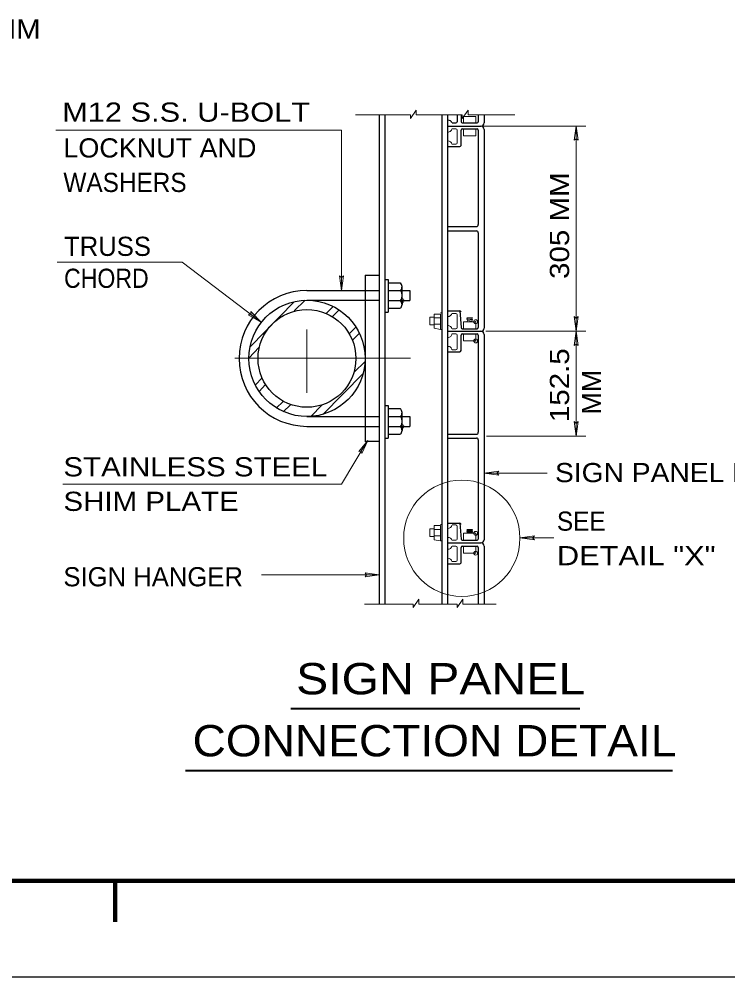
# Model space of a CAD drawing. Extents: x 312601.858 to 312602.699, y 144420.109 to 144420.704.
# Drawn here: x 312602.2633 to 312602.3741, y 144420.1095 to 144420.2593 of the extents above; entities that cross this region are included whole.
import ezdxf
from ezdxf.enums import TextEntityAlignment as Align

# ---------------------------------------------------------------- set-up
doc = ezdxf.new("R2010")
doc.units = 0
doc.header["$LTSCALE"] = 0.0012
doc.header["$PDMODE"] = 32
doc.header["$PDSIZE"] = 0.0006
doc.linetypes.add('DOT_DASHED', pattern=[7.7, 5, -1.2, 0.3, -1.2])
doc.linetypes.add('SHORT_DASHED', pattern=[2.7, 1.5, -1.2])
for name, color, linetype, lineweight in [('1', 7, 'Continuous', 13), ('2', 7, 'Continuous', 13), ('39', 7, 'Continuous', 13)]:
    doc.layers.add(name, color=color, linetype=linetype, lineweight=lineweight)

msp = doc.modelspace()

# ---------------------------------------------------------------- hatches: boundary and pattern name
at = {"layer": '39'}
msp.add_hatch(color=256, dxfattribs=at).paths.add_polyline_path([(312602.2995, 144420.2132), (312602.2995, 144420.2136), (312602.3012, 144420.2119), (312602.2991, 144420.2131)])

# ---------------------------------------------------------------- linework, layer by layer
at = {"layer": '1'}
for p, q in [((312602.3159, 144420.2444), (312602.3245, 144420.2444)), ((312602.3245, 144420.2438), (312602.3254, 144420.2451)), ((312602.3245, 144420.2438), (312602.3245, 144420.2444)), ((312602.3254, 144420.2444), (312602.3254, 144420.2451)), ((312602.3254, 144420.2444), (312602.3326, 144420.2444)), ((312602.3326, 144420.2438), (312602.3335, 144420.2451)), ((312602.3326, 144420.2438), (312602.3326, 144420.2444)), ((312602.3328, 144420.2441), (312602.3328, 144420.2431)), ((312602.3328, 144420.2441), (312602.3347, 144420.2441)), ((312602.3335, 144420.2444), (312602.3335, 144420.2451)), ((312602.3335, 144420.2444), (312602.3408, 144420.2444)), ((312602.3347, 144420.2441), (312602.3347, 144420.2431)), ((312602.3351, 144420.2444), (312602.3351, 144420.2432)), ((312602.269, 144420.242), (312602.3137, 144420.242)), ((312602.3137, 144420.242), (312602.3137, 144420.2169)), ((312602.331, 144420.2422), (312602.3316, 144420.2422)), ((312602.3318, 144420.24), (312602.3318, 144420.242)), ((312602.3328, 144420.2411), (312602.3328, 144420.2422)), ((312602.3328, 144420.2411), (312602.3347, 144420.2411)), ((312602.3347, 144420.2411), (312602.3347, 144420.2422)), ((312602.331, 144420.2398), (312602.3316, 144420.2398)), ((312602.2994, 144420.2081), (312602.3063, 144420.2151)), ((312602.3063, 144420.2137), (312602.308, 144420.2154)), ((312602.3113, 144420.2133), (312602.3124, 144420.2144)), ((312602.3123, 144420.2128), (312602.3133, 144420.2138)), ((312602.3275, 144420.2127), (312602.3275, 144420.2115)), ((312602.3282, 144420.2127), (312602.3275, 144420.2127)), ((312602.3294, 144420.2134), (312602.3292, 144420.2134)), ((312602.331, 144420.2133), (312602.3316, 144420.2133)), ((312602.3318, 144420.2131), (312602.3318, 144420.2111)), ((312602.3149, 144420.2101), (312602.316, 144420.2112)), ((312602.3282, 144420.2115), (312602.3275, 144420.2115)), ((312602.3282, 144420.2126), (312602.3292, 144420.2126)), ((312602.3282, 144420.2116), (312602.3292, 144420.2116)), ((312602.3328, 144420.212), (312602.3328, 144420.2109)), ((312602.3328, 144420.212), (312602.3347, 144420.212)), ((312602.3333, 144420.2126), (312602.3334, 144420.2126)), ((312602.3333, 144420.2124), (312602.3341, 144420.2124)), ((312602.3334, 144420.2126), (312602.3341, 144420.2126)), ((312602.3334, 144420.2122), (312602.3342, 144420.2123)), ((312602.3347, 144420.212), (312602.3347, 144420.2109)), ((312602.3154, 144420.2091), (312602.3165, 144420.2102)), ((312602.3294, 144420.2108), (312602.3292, 144420.2108)), ((312602.331, 144420.2109), (312602.3316, 144420.2109)), ((312602.331, 144420.2101), (312602.3316, 144420.2101)), ((312602.3318, 144420.2078), (312602.3318, 144420.2099)), ((312602.3327, 144420.2109), (312602.3349, 144420.2109)), ((312602.3327, 144420.2101), (312602.3349, 144420.2101)), ((312602.3328, 144420.209), (312602.3328, 144420.2101)), ((312602.3347, 144420.209), (312602.3347, 144420.2101)), ((312602.3363, 144420.2105), (312602.3519, 144420.2105)), ((312602.3328, 144420.209), (312602.3347, 144420.209)), ((312602.2992, 144420.2063), (312602.3008, 144420.208)), ((312602.331, 144420.2076), (312602.3316, 144420.2076)), ((312602.3157, 144420.2041), (312602.3174, 144420.2058)), ((312602.3108, 144420.1975), (312602.3171, 144420.2039)), ((312602.3002, 144420.2021), (312602.3013, 144420.2032)), ((312602.3008, 144420.2011), (312602.3018, 144420.2022)), ((312602.3035, 144420.1985), (312602.3046, 144420.1995)), ((312602.3046, 144420.1979), (312602.3057, 144420.199)), ((312602.3089, 144420.1972), (312602.3107, 144420.199)), ((312602.3177, 144420.1933), (312602.3137, 144420.1866)), ((312602.3364, 144420.1941), (312602.3519, 144420.1941)), ((312602.336, 144420.1883), (312602.3459, 144420.1883)), ((312602.2701, 144420.1866), (312602.3137, 144420.1866)), ((312602.3294, 144420.1803), (312602.3292, 144420.1803)), ((312602.331, 144420.1802), (312602.3316, 144420.1802)), ((312602.3318, 144420.18), (312602.3318, 144420.178)), ((312602.3275, 144420.1796), (312602.3275, 144420.1784)), ((312602.3282, 144420.1796), (312602.3275, 144420.1796)), ((312602.3282, 144420.1784), (312602.3275, 144420.1784)), ((312602.3282, 144420.1795), (312602.3292, 144420.1795)), ((312602.3282, 144420.1785), (312602.3292, 144420.1785)), ((312602.3328, 144420.1789), (312602.3328, 144420.1778)), ((312602.3328, 144420.1789), (312602.3347, 144420.1789)), ((312602.3333, 144420.1794), (312602.3334, 144420.1795)), ((312602.3333, 144420.1792), (312602.3341, 144420.1792)), ((312602.3334, 144420.1795), (312602.3342, 144420.1795)), ((312602.3334, 144420.1793), (312602.3342, 144420.1793)), ((312602.3334, 144420.1791), (312602.3342, 144420.1791)), ((312602.3347, 144420.1789), (312602.3347, 144420.1778)), ((312602.3416, 144420.1782), (312602.3469, 144420.1782)), ((312602.3294, 144420.1777), (312602.3292, 144420.1777)), ((312602.331, 144420.1778), (312602.3316, 144420.1778)), ((312602.331, 144420.1769), (312602.3316, 144420.1769)), ((312602.3318, 144420.1747), (312602.3318, 144420.1767)), ((312602.3327, 144420.1778), (312602.3349, 144420.1778)), ((312602.3328, 144420.1758), (312602.3328, 144420.1769)), ((312602.3347, 144420.1758), (312602.3347, 144420.1769)), ((312602.3328, 144420.1758), (312602.3347, 144420.1758)), ((312602.331, 144420.1745), (312602.3316, 144420.1745)), ((312602.3012, 144420.1724), (312602.3196, 144420.1724)), ((312602.3173, 144420.1678), (312602.3249, 144420.1678)), ((312602.3249, 144420.1673), (312602.3258, 144420.1686)), ((312602.3249, 144420.1673), (312602.3249, 144420.1678)), ((312602.3258, 144420.1678), (312602.3258, 144420.1686)), ((312602.3258, 144420.1678), (312602.3318, 144420.1678)), ((312602.3318, 144420.1673), (312602.3327, 144420.1686)), ((312602.3318, 144420.1673), (312602.3318, 144420.1678)), ((312602.3327, 144420.1678), (312602.3327, 144420.1686)), ((312602.3327, 144420.1678), (312602.3379, 144420.1678))]:
    msp.add_line(p, q, dxfattribs=at)
at = {"layer": '1', "lineweight": 25}
for p, q in [((312602.3196, 144420.2444), (312602.3196, 144420.1678)), ((312602.3205, 144420.2444), (312602.3205, 144420.1678)), ((312602.3294, 144420.2444), (312602.3294, 144420.1678)), ((312602.3303, 144420.2444), (312602.3303, 144420.2272)), ((312602.3318, 144420.2444), (312602.3318, 144420.2433)), ((312602.3324, 144420.2444), (312602.3324, 144420.2433)), ((312602.3351, 144420.2444), (312602.3351, 144420.2433)), ((312602.336, 144420.2444), (312602.336, 144420.2431)), ((312602.3303, 144420.2426), (312602.3355, 144420.2426)), ((312602.331, 144420.2431), (312602.3316, 144420.2431)), ((312602.3326, 144420.2431), (312602.3349, 144420.2431)), ((312602.3324, 144420.2396), (312602.3324, 144420.242)), ((312602.3326, 144420.2422), (312602.3349, 144420.2422)), ((312602.3351, 144420.242), (312602.3351, 144420.2282)), ((312602.3351, 144420.242), (312602.3351, 144420.2272)), ((312602.336, 144420.2421), (312602.336, 144420.211)), ((312602.3303, 144420.2394), (312602.3322, 144420.2394)), ((312602.3303, 144420.2272), (312602.3303, 144420.1947)), ((312602.3303, 144420.2269), (312602.3348, 144420.2269)), ((312602.3303, 144420.2262), (312602.3348, 144420.2262)), ((312602.3351, 144420.2259), (312602.3351, 144420.2111)), ((312602.3351, 144420.2248), (312602.3351, 144420.2111)), ((312602.3174, 144420.2193), (312602.3174, 144420.1932)), ((312602.3174, 144420.2193), (312602.3196, 144420.2193)), ((312602.3205, 144420.2186), (312602.321, 144420.2186)), ((312602.321, 144420.2181), (312602.3229, 144420.2181)), ((312602.3232, 144420.2169), (312602.3232, 144420.2175)), ((312602.3083, 144420.2169), (312602.3174, 144420.2169)), ((312602.321, 144420.2169), (312602.323, 144420.2169)), ((312602.323, 144420.2169), (312602.3232, 144420.2169)), ((312602.3232, 144420.2153), (312602.3232, 144420.2169)), ((312602.3244, 144420.2169), (312602.3244, 144420.2153)), ((312602.3083, 144420.2154), (312602.3174, 144420.2154)), ((312602.323, 144420.2153), (312602.3232, 144420.2153)), ((312602.3232, 144420.2153), (312602.3232, 144420.2147)), ((312602.3205, 144420.2135), (312602.321, 144420.2135)), ((312602.321, 144420.2141), (312602.3229, 144420.2141)), ((312602.3303, 144420.2105), (312602.3357, 144420.2105)), ((312602.3324, 144420.2075), (312602.3324, 144420.2099)), ((312602.3326, 144420.2109), (312602.3349, 144420.2109)), ((312602.3326, 144420.2101), (312602.3349, 144420.2101)), ((312602.3351, 144420.2099), (312602.3351, 144420.1947)), ((312602.336, 144420.21), (312602.336, 144420.1779)), ((312602.3303, 144420.2073), (312602.3322, 144420.2073)), ((312602.3205, 144420.1989), (312602.321, 144420.1989)), ((312602.321, 144420.1984), (312602.3229, 144420.1984)), ((312602.3232, 144420.1972), (312602.3232, 144420.1978)), ((312602.3083, 144420.1972), (312602.3174, 144420.1972)), ((312602.321, 144420.1972), (312602.323, 144420.1972)), ((312602.323, 144420.1972), (312602.3232, 144420.1972)), ((312602.3232, 144420.1956), (312602.3232, 144420.1972)), ((312602.3244, 144420.1972), (312602.3244, 144420.1956)), ((312602.3083, 144420.1956), (312602.3174, 144420.1956)), ((312602.323, 144420.1956), (312602.3232, 144420.1956)), ((312602.3232, 144420.1956), (312602.3232, 144420.195)), ((312602.3303, 144420.1947), (312602.3303, 144420.1678)), ((312602.3174, 144420.1933), (312602.3196, 144420.1933)), ((312602.3205, 144420.1938), (312602.321, 144420.1938)), ((312602.321, 144420.1944), (312602.3229, 144420.1944)), ((312602.3303, 144420.1944), (312602.3348, 144420.1944)), ((312602.3303, 144420.1938), (312602.3348, 144420.1938)), ((312602.3351, 144420.1935), (312602.3351, 144420.178)), ((312602.3351, 144420.1932), (312602.3351, 144420.178)), ((312602.3303, 144420.1774), (312602.3355, 144420.1774)), ((312602.3324, 144420.1743), (312602.3324, 144420.1767)), ((312602.3326, 144420.1778), (312602.3349, 144420.1778)), ((312602.3326, 144420.1769), (312602.3349, 144420.1769)), ((312602.3327, 144420.1769), (312602.3349, 144420.1769)), ((312602.3351, 144420.1767), (312602.3351, 144420.1678)), ((312602.336, 144420.1769), (312602.336, 144420.1678)), ((312602.3303, 144420.1741), (312602.3322, 144420.1741))]:
    msp.add_line(p, q, dxfattribs=at)
at = {"layer": '1', "linetype": 'SHORT_DASHED', "lineweight": 25}
for p, q in [((312602.3174, 144420.2169), (312602.3196, 144420.2169)), ((312602.3174, 144420.2154), (312602.3196, 144420.2154)), ((312602.3174, 144420.1972), (312602.3196, 144420.1972)), ((312602.3174, 144420.1956), (312602.3196, 144420.1956))]:
    msp.add_line(p, q, dxfattribs=at)
at = {"layer": '1', "linetype": 'DOT_DASHED'}
for p, q in [((312602.3083, 144420.2009), (312602.3083, 144420.2108)), ((312602.297, 144420.2063), (312602.3245, 144420.2063))]:
    msp.add_line(p, q, dxfattribs=at)
at = {"layer": '1'}
for points in [[(312602.3303, 144420.2426), (312602.3357, 144420.2426), (312602.3519, 144420.2426)], [(312602.3504, 144420.2426), (312602.3504, 144420.2105), (312602.3504, 144420.1941)], [(312602.3333, 144420.212), (312602.3334, 144420.2122), (312602.3333, 144420.2124), (312602.3334, 144420.2125), (312602.3333, 144420.2126)], [(312602.3333, 144420.212), (312602.3341, 144420.2121), (312602.3341, 144420.2121)], [(312602.3334, 144420.2126), (312602.3342, 144420.2126), (312602.3341, 144420.2126)], [(312602.3341, 144420.2121), (312602.3342, 144420.2123), (312602.3341, 144420.2124), (312602.3342, 144420.2126)], [(312602.3333, 144420.1794), (312602.3341, 144420.1794), (312602.3342, 144420.1791), (312602.3341, 144420.1792)], [(312602.3333, 144420.1789), (312602.3334, 144420.1791), (312602.3333, 144420.1792), (312602.3334, 144420.1793), (312602.3333, 144420.1794)], [(312602.3333, 144420.1789), (312602.3341, 144420.179), (312602.3341, 144420.179)], [(312602.3341, 144420.1792), (312602.3342, 144420.1793), (312602.3341, 144420.1794), (312602.3342, 144420.1795)], [(312602.3303, 144420.1774), (312602.3346, 144420.1774), (312602.3355, 144420.1774)]]:
    msp.add_lwpolyline(points, dxfattribs=at)
for points in [[(312602.3501, 144420.2404), (312602.3504, 144420.2426), (312602.3507, 144420.2404), (312602.3504, 144420.2406)], [(312602.314, 144420.2192), (312602.3137, 144420.2169), (312602.3134, 144420.2192), (312602.3137, 144420.2189)], [(312602.3282, 144420.2132), (312602.3292, 144420.2132), (312602.3292, 144420.2108), (312602.3282, 144420.211)], [(312602.3507, 144420.2128), (312602.3504, 144420.2105), (312602.3501, 144420.2128), (312602.3504, 144420.2125)], [(312602.3501, 144420.2083), (312602.3504, 144420.2105), (312602.3507, 144420.2083), (312602.3504, 144420.2085)], [(312602.3507, 144420.1964), (312602.3504, 144420.1941), (312602.3501, 144420.1964), (312602.3504, 144420.1961)], [(312602.3164, 144420.1917), (312602.3178, 144420.1934), (312602.3169, 144420.1914), (312602.3168, 144420.1918)], [(312602.3383, 144420.188), (312602.336, 144420.1883), (312602.3383, 144420.1886), (312602.338, 144420.1883)], [(312602.3282, 144420.1801), (312602.3292, 144420.1801), (312602.3292, 144420.1777), (312602.3282, 144420.1779)], [(312602.3439, 144420.1779), (312602.3416, 144420.1782), (312602.3439, 144420.1785), (312602.3436, 144420.1782)], [(312602.3174, 144420.1727), (312602.3196, 144420.1724), (312602.3174, 144420.1721), (312602.3176, 144420.1724)]]:
    msp.add_lwpolyline(points, close=True, dxfattribs=at)
at = {"layer": '1', "lineweight": 25}
for points in [[(312602.323, 144420.2169), (312602.3232, 144420.2169), (312602.3244, 144420.2169)], [(312602.321, 144420.2153), (312602.323, 144420.2153), (312602.3244, 144420.2153)], [(312602.3303, 144420.2137), (312602.3322, 144420.2137), (312602.3324, 144420.2111)], [(312602.323, 144420.1972), (312602.3232, 144420.1972), (312602.3244, 144420.1972)], [(312602.321, 144420.1956), (312602.323, 144420.1956), (312602.3244, 144420.1956)], [(312602.3303, 144420.1805), (312602.3322, 144420.1805), (312602.3324, 144420.178)]]:
    msp.add_lwpolyline(points, dxfattribs=at)
for radius in [0.009095, 0.00765]:
    msp.add_circle((312602.3083, 144420.20626), radius, dxfattribs=at)
at = {"layer": '1'}
msp.add_circle((312602.332525, 144420.178125), 0.009095, dxfattribs=at)
at = {"layer": '1', "lineweight": 25}
for centre, radius, start, end in [((312602.3316, 144420.2433), 0.0002, 270, 0), ((312602.3326, 144420.2433), 0.0002, 180, 270), ((312602.3349, 144420.2433), 0.0002, 270, 0), ((312602.3355, 144420.2431), 0.0005, 270, 0), ((312602.3355, 144420.2421), 0.0005, 0, 90), ((312602.3326, 144420.242), 0.0002, 90, 180), ((312602.3349, 144420.242), 0.0002, 0, 90), ((312602.3322, 144420.2396), 0.0002, 270, 0), ((312602.3348, 144420.2272), 0.0003, 270, 0), ((312602.3348, 144420.2259), 0.0003, 0, 90), ((312602.32223, 144420.21746), 0.000939, 323.38244, 42.97513), ((312602.32223, 144420.21746), 0.000939, 323.38244, 2.44183), ((312602.3083, 144420.20626), 0.010625, 90, 270), ((312602.3215, 144420.2161), 0.0017, 331.92751, 28.07248), ((312602.32223, 144420.21474), 0.000939, 317.02487, 356.82121), ((312602.32223, 144420.21474), 0.000939, 357.55817, 36.61756), ((312602.3322, 144420.2135), 0.0002, 0, 90), ((312602.3326, 144420.2111), 0.0002, 180, 270), ((312602.3326, 144420.2099), 0.0002, 90, 180), ((312602.3349, 144420.2111), 0.0002, 270, 0), ((312602.3349, 144420.2099), 0.0002, 0, 90), ((312602.3355, 144420.211), 0.0005, 270, 0), ((312602.3355, 144420.21), 0.0005, 0, 90), ((312602.3322, 144420.2075), 0.0002, 270, 0), ((312602.32223, 144420.19776), 0.000939, 323.38244, 42.97513), ((312602.32223, 144420.19776), 0.000939, 323.38244, 2.44183), ((312602.3215, 144420.1964), 0.0017, 331.92751, 28.07248), ((312602.32223, 144420.19504), 0.000939, 317.02487, 356.82121), ((312602.32223, 144420.19504), 0.000939, 357.55817, 36.61756), ((312602.3348, 144420.1947), 0.0003, 270, 0), ((312602.3348, 144420.1935), 0.0003, 0, 90), ((312602.3322, 144420.1803), 0.0002, 0, 90), ((312602.3326, 144420.178), 0.0002, 180, 270), ((312602.3326, 144420.1767), 0.0002, 90, 180), ((312602.3349, 144420.178), 0.0002, 270, 0), ((312602.3349, 144420.1767), 0.0002, 0.00156, 90), ((312602.3355, 144420.1779), 0.0005, 270, 0), ((312602.3355, 144420.1769), 0.0005, 0, 90), ((312602.3322, 144420.1743), 0.0002, 270, 0)]:
    msp.add_arc(centre, radius, start, end, dxfattribs=at)
at = {"layer": '1'}
for centre, start, end in [((312602.3316, 144420.242), 0, 90), ((312602.3316, 144420.24), 270, 0), ((312602.3316, 144420.2131), 0, 90), ((312602.3316, 144420.2111), 270, 0), ((312602.3316, 144420.2099), 0, 90), ((312602.3316, 144420.2078), 270, 0), ((312602.3316, 144420.18), 0, 90), ((312602.3316, 144420.178), 270, 0), ((312602.3316, 144420.1767), 0, 90), ((312602.3316, 144420.1747), 270, 0)]:
    msp.add_arc(centre, 0.0002, start, end, dxfattribs=at)
at = {"layer": '1', "lineweight": 25}
msp.add_ellipse((312602.330308, 144420.243036), major_axis=(0.000656, 0), ratio=0.777881, start_param=0.1253975, end_param=1.5707963, dxfattribs=at)
at = {"layer": '1'}
for centre, start_param, end_param in [((312602.330308, 144420.242186), 4.712389, 6.3105715), ((312602.330308, 144420.239777), 0.0446785, 1.5707963), ((312602.330308, 144420.213315), 4.712389, 6.2831853), ((312602.330308, 144420.210906), 6.2710267, 7.8539816), ((312602.330308, 144420.210056), 4.712389, 6.3694869), ((312602.330308, 144420.207647), 6.1904888, 7.8539816), ((312602.330308, 144420.180165), 4.712389, 6.2831853), ((312602.330308, 144420.177756), 0.0859671, 1.5707963), ((312602.330308, 144420.176906), 4.712389, 6.2831853), ((312602.330308, 144420.174497), 0, 1.5707963)]:
    msp.add_ellipse(centre, major_axis=(0.000656, 0), ratio=0.777881, start_param=start_param, end_param=end_param, dxfattribs=at)
for p in [(312602.3232, 144420.2153), (312602.3347, 144420.212), (312602.3347, 144420.209), (312602.3232, 144420.1956), (312602.3347, 144420.1789), (312602.3347, 144420.1758)]:
    msp.add_point(p, dxfattribs=at)
at = {"layer": '2', "lineweight": 25}
for p, q in [((312602.321, 144420.2186), (312602.321, 144420.2135)), ((312602.321, 144420.1989), (312602.321, 144420.1938))]:
    msp.add_line(p, q, dxfattribs=at)
at = {"layer": '2', "lineweight": 40}
for p, q in [((312602.3058, 144420.1515), (312602.351, 144420.1515)), ((312602.2893, 144420.1418), (312602.3655, 144420.1418))]:
    msp.add_line(p, q, dxfattribs=at)
at = {"layer": '2'}
msp.add_lwpolyline([(312602.3012, 144420.2119), (312602.2888, 144420.2213), (312602.2692, 144420.2213)], dxfattribs=at)
at = {"layer": '39', "lineweight": 158}
for p, q in [((312601.9088, 144420.1245), (312602.6838, 144420.1245)), ((312602.2783, 144420.1181), (312602.2783, 144420.1245)), ((312602.2783, 144420.1181), (312602.2783, 144420.1245)), ((312602.2783, 144420.1181), (312602.2783, 144420.1245))]:
    msp.add_line(p, q, dxfattribs=at)
at = {"layer": '39', "lineweight": 25}
msp.add_line((312601.8578, 144420.1095), (312602.6988, 144420.1095), dxfattribs=at)
at = {"layer": '39'}
msp.add_lwpolyline([(312602.2995, 144420.2132), (312602.2995, 144420.2136), (312602.3012, 144420.2119), (312602.2991, 144420.2131)], close=True, dxfattribs=at)

# ---------------------------------------------------------------- texts
at = {"layer": '2', "width": 1.15}
msp.add_text('50 MM', height=0.003, dxfattribs=at).set_placement((312602.2596, 144420.2563), align=Align.CENTER)
at = {"layer": '2'}
for s, height, width, p in [('M12 S.S. U-BOLT', 0.003, 1.2, (312602.27, 144420.2433)), ('LOCKNUT AND', 0.003, 1.05, (312602.2702, 144420.2377)), ('WASHERS', 0.003, 0.95, (312602.2702, 144420.2323)), ('CHORD', 0.003, 0.9, (312602.2703, 144420.2173)), ('STAINLESS STEEL', 0.003, 1.15, (312602.2702, 144420.1878)), ('SIGN PANEL FACE', 0.003, 1.1, (312602.3471, 144420.1869)), ('SHIM PLATE', 0.003, 1.15, (312602.2702, 144420.1824)), ('SEE', 0.003, 0.95, (312602.3474, 144420.1793)), ('DETAIL "X"', 0.003, 1.2, (312602.3474, 144420.1739)), ('SIGN PANEL ', 0.0049, 1.15, (312602.3066, 144420.1537)), ('CONNECTION DETAIL ', 0.0049, 1.1, (312602.2904, 144420.144))]:
    msp.add_text(s, height=height, dxfattribs=dict(at, width=width)).set_placement(p)
for s, width, p in [('305 MM', 1.15, (312602.3493, 144420.2187)), ('152.5', 1.15, (312602.3493, 144420.1963)), (' MM', 1.05, (312602.3543, 144420.1963))]:
    msp.add_text(s, height=0.003, rotation=90, dxfattribs=dict(at, width=width)).set_placement(p)
for s, p in [('TRUSS', (312602.2703, 144420.2223)), ('SIGN HANGER', (312602.2702, 144420.1706))]:
    msp.add_text(s, height=0.003, dxfattribs=at).set_placement(p)

doc.saveas('drawing.dxf')
